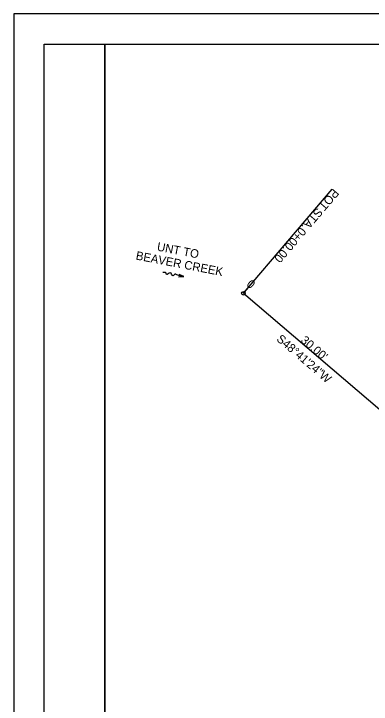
# Model space of a CAD drawing. Extents: x 0 to 2765, y 0 to 220.
# Drawn here: x 0 to 58.9, y 106.4 to 220 of the extents above; entities that cross this region are included whole.
import ezdxf

# ---------------------------------------------------------------- set-up
doc = ezdxf.new("R2010")
doc.units = 0
for name, color, linetype in [('DR_P_Erosion_Control', 7, 'Continuous'), ('DR_X_Culvert', 7, 'Continuous'), ('HY_P_Water_Edge', 7, 'Continuous'), ('MT_P_Edge_Line', 7, 'Continuous'), ('MT_P_PCB', 7, 'Continuous'), ('MT_P_Temp_Road', 7, 'Continuous'), ('MT_P_Transverse_Line', 7, 'Continuous'), ('MT_P_Work_Area', 7, 'Continuous'), ('PF_X_Ground_Line', 7, 'Continuous')]:
    doc.layers.add(name, color=color, linetype=linetype)

msp = doc.modelspace()

# ---------------------------------------------------------------- linework, layer by layer
at = {"layer": 'DR_X_Culvert'}
msp.add_lwpolyline([(0, 0), (340, 0), (340, 220), (0, 220)], close=True, dxfattribs=at)
at = {"layer": 'HY_P_Water_Edge'}
for p, q in [((27.16, 176.7), (27.99, 176.76)), ((27.99, 176.76), (27.24, 177.12))]:
    msp.add_line(p, q, dxfattribs=at)
msp.add_spline([(27.99, 176.76), (27.17, 176.91), (26.86, 177.05), (26.67, 177.16), (26.19, 176.88), (25.79, 177.38), (25.16, 177.08), (25.09, 177.32), (24.55, 177.41)], degree=3, dxfattribs=at)
at = {"layer": 'MT_P_Edge_Line'}
msp.add_line((37.84, 174), (38.48, 174.76), dxfattribs=at)
at = {"layer": 'MT_P_PCB'}
msp.add_line((37.84, 174), (52.44, 191.12), dxfattribs=at)
msp.add_circle((37.84, 174), 0.3, dxfattribs=at)
at = {"layer": 'MT_P_Work_Area'}
msp.add_line((37.84, 174), (60.66, 154.53), dxfattribs=at)
at = {"layer": 'PF_X_Ground_Line'}
for points in [[(5, 215), (15, 215), (15, 5), (5, 5)], [(15, 215), (335, 215), (335, 5), (15, 5)]]:
    msp.add_lwpolyline(points, close=True, dxfattribs=at)

# ---------------------------------------------------------------- texts
at = {"layer": 'DR_P_Erosion_Control'}
for s, p in [('UNT TO', (23.51, 181.04)), ('BEAVER CREEK', (20.02, 179.57))]:
    msp.add_text(s, height=1.4, rotation=349.1589, dxfattribs=at).set_placement(p)
at = {"layer": 'MT_P_Edge_Line'}
msp.add_text('0', height=1.4, rotation=319.5399, dxfattribs=at).set_placement((38.22, 175.31))
at = {"layer": 'MT_P_PCB'}
for s, p in [('POT', (52.63, 191.32)), (' STA. ', (50.3, 188.58)), ('0+00.00', (47.23, 184.98))]:
    msp.add_text(s, height=1.4, rotation=229.5399, dxfattribs=at).set_placement(p)
at = {"layer": 'MT_P_Temp_Road'}
msp.add_text("30.00'", height=1.4, rotation=319.5399, dxfattribs=at).set_placement((47.15, 166.08))
at = {"layer": 'MT_P_Transverse_Line'}
msp.add_text('S48°41\'24"W', height=1.4, rotation=319.5399, dxfattribs=at).set_placement((43.17, 166.29))

doc.saveas('drawing.dxf')
